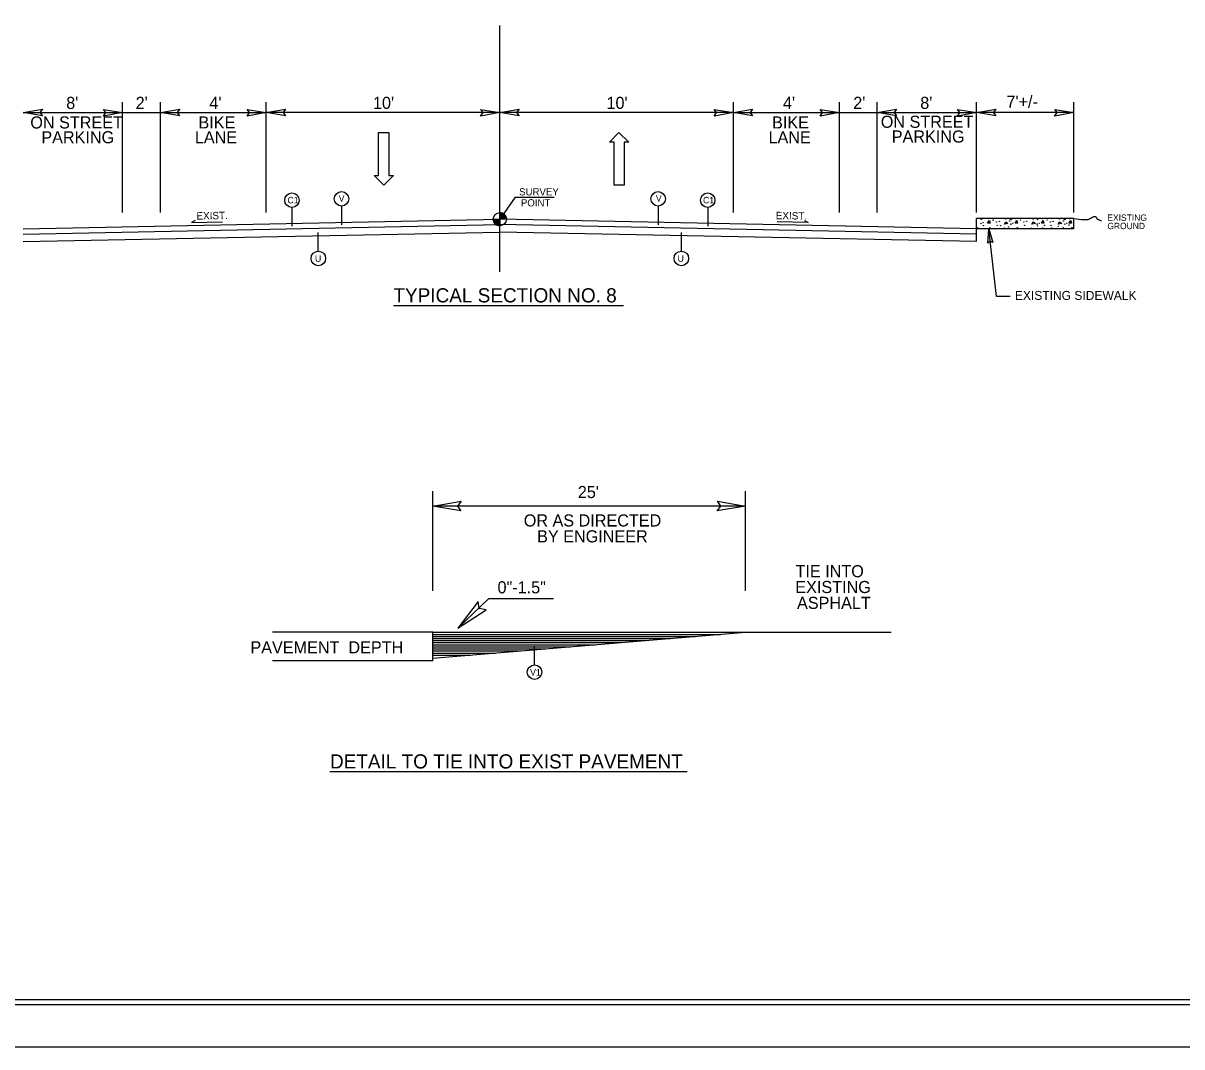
# Model space of a CAD drawing. Extents: x 1022283 to 1026986, y 174822 to 180471.
# Drawn here: x 1023200 to 1024733, y 174822 to 176176 of the extents above; entities that cross this region are included whole.
import ezdxf

# ---------------------------------------------------------------- set-up
doc = ezdxf.new("R2010")
doc.units = 0
for name, color, linetype in [('Default', 7, 'Continuous'), ('Old_Level_3', 7, 'Continuous'), ('Prop Dimension', 7, 'Continuous'), ('Prop Lane Arrow CELL', 7, 'Continuous'), ('Prop Terminator CELL', 7, 'Continuous'), ('Sheet Cutting Line CELL', 7, 'Continuous'), ('Sheet Plot Border Inside CELL', 7, 'Continuous'), ('Sheet Plot Border Outside CELL', 7, 'Continuous'), ('Sheet Typical CELL', 7, 'Continuous'), ('Typical Berm Information CELL', 7, 'Continuous'), ('Typical Curb CELL', 7, 'Continuous'), ('Typical Grade Point Symbol CELL', 7, 'Continuous'), ('Typical ID Circle CELL', 7, 'Continuous'), ('Typical Slope Point Local CELL', 7, 'Continuous'), ('Typical Text General CELL', 7, 'Continuous'), ('Typical Text Grade Point CELL', 7, 'Continuous'), ('Typical Text ID Circle CELL', 7, 'Continuous'), ('Typical Text Label CELL', 7, 'Continuous')]:
    doc.layers.add(name, color=color, linetype=linetype)

# ---------------------------------------------------------------- blocks, each defined once
blk = doc.blocks.new('Lane Arrow Through')
at = {"layer": 'Prop Lane Arrow CELL'}
for p, q in [((-17.15, 1.6), (-3.15, 1.6)), ((-17.15, -1.7), (-17.15, 1.6)), ((-3.15, 1.6), (-3.15, 3.1)), ((-3.15, 3.1), (0, 0)), ((0, 0), (-3.15, -3.2)), ((-3.15, -1.7), (-17.15, -1.7)), ((-3.15, -3.2), (-3.15, -1.7))]:
    blk.add_line(p, q, dxfattribs=at)
blk = doc.blocks.new('Terminator')
at = {"layer": 'Prop Terminator CELL'}
blk.add_lwpolyline([(-9, 1.55), (0, 0), (-9.05, -1.6), (-7.9, 0)], close=True, dxfattribs=at)

msp = doc.modelspace()

# ---------------------------------------------------------------- linework, layer by layer
at = {"layer": 'Default'}
for p, q in [((1023331.7, 175925.5), (1023331.7, 176071.8)), ((1023381.7, 175925.5), (1023381.7, 176071.8)), ((1023521.7, 175925.5), (1023521.7, 176071.8)), ((1023830.5, 175925.5), (1023830.5, 176071.8)), ((1024139.4, 175925.5), (1024139.4, 176071.8)), ((1024279.7, 175925.5), (1024279.7, 176071.8)), ((1024329.7, 175925.5), (1024329.7, 176071.8)), ((1024460.9, 175925.5), (1024460.9, 176071.8)), ((1024589.7, 175925.5), (1024589.7, 176071.8)), ((1024589.7, 175925.5), (1024589.7, 176071.8)), ((1023200.2, 176057.8), (1023331.7, 176057.8)), ((1023331.7, 176057.8), (1023381.7, 176057.8)), ((1023381.7, 176057.8), (1023521.7, 176057.8)), ((1023830.5, 176057.8), (1023521.7, 176057.8)), ((1024139.4, 176057.8), (1023830.5, 176057.8)), ((1024139.4, 176057.8), (1024279.7, 176057.8)), ((1024279.7, 176057.8), (1024329.7, 176057.8)), ((1024329.7, 176057.8), (1024461.3, 176057.8)), ((1024589.7, 176057.8), (1024460.9, 176057.8)), ((1023742, 175425.4), (1023742, 175557.1)), ((1024155.3, 175425.4), (1024155.3, 175557.1)), ((1024155.3, 175537.6), (1023742, 175537.6)), ((1023774.9, 175376.2), (1023816, 175415.5)), ((1023816, 175415.5), (1023901.6, 175415.5))]:
    msp.add_line(p, q, dxfattribs=at)
at = {"layer": 'Old_Level_3'}
for p, q in [((1023742, 175370.7), (1023530, 175370.7)), ((1023742, 175370.7), (1024155.3, 175370.7)), ((1023742, 175370.7), (1024348.1, 175370.7)), ((1023742, 175336.2), (1023742, 175370.7)), ((1023742, 175336.2), (1024155.3, 175370.7)), ((1023742, 175332.9), (1023742, 175370.7)), ((1023742, 175367.9), (1024122.2, 175367.9)), ((1023742, 175365.2), (1024089.1, 175365.2)), ((1023742, 175362.4), (1024056.1, 175362.4)), ((1023742, 175359.7), (1024023, 175359.7)), ((1023742, 175356.9), (1023990, 175356.9)), ((1023742, 175354.1), (1023956.9, 175354.1)), ((1023742, 175351.4), (1023923.8, 175351.4)), ((1023742, 175348.6), (1023890.8, 175348.6)), ((1023742, 175332.9), (1023530, 175332.9)), ((1023742, 175345.9), (1023857.7, 175345.9)), ((1023742, 175343.1), (1023824.7, 175343.1)), ((1023742, 175340.4), (1023791.6, 175340.4))]:
    msp.add_line(p, q, dxfattribs=at)
at = {"layer": 'Prop Dimension'}
for p, q in [((1023830.5, 176082.4), (1023830.5, 176173.1)), ((1023830.5, 176048.4), (1023830.5, 176082.4)), ((1023830.5, 175847.3), (1023830.5, 176048.4)), ((1023850.8, 175946), (1023830.5, 175916.8)), ((1023200.2, 175904.2), (1023830.5, 175916.8)), ((1024460.9, 175904.2), (1023830.5, 175916.8)), ((1023200.2, 175897.2), (1023830.5, 175909.8)), ((1023200.2, 175887.2), (1023830.5, 175899.8)), ((1024460.9, 175897.2), (1023830.5, 175909.8)), ((1024460.9, 175887.2), (1023830.5, 175899.8)), ((1024487.4, 175814.5), (1024477.1, 175904.2)), ((1024505.6, 175814.5), (1024487.4, 175814.5))]:
    msp.add_line(p, q, dxfattribs=at)
at = {"layer": 'Prop Terminator CELL'}
for points in [[(1023225.5, 176053.4), (1023200.2, 176057.8), (1023225.6, 176062.3), (1023222.4, 176057.8)], [(1023306.4, 176062.1), (1023331.7, 176057.8), (1023306.3, 176053.3), (1023309.5, 176057.8)], [(1023407, 176053.4), (1023381.7, 176057.8), (1023407.2, 176062.3), (1023403.9, 176057.8)], [(1023496.4, 176062.1), (1023521.7, 176057.8), (1023496.3, 176053.3), (1023499.5, 176057.8)], [(1023547, 176053.4), (1023521.7, 176057.8), (1023547.2, 176062.3), (1023543.9, 176057.8)], [(1023805.2, 176062.1), (1023830.5, 176057.8), (1023805.1, 176053.3), (1023808.3, 176057.8)], [(1023855.9, 176053.4), (1023830.5, 176057.8), (1023856, 176062.3), (1023852.8, 176057.8)], [(1024114, 176062.1), (1024139.4, 176057.8), (1024113.9, 176053.3), (1024117.1, 176057.8)], [(1024164.7, 176053.4), (1024139.4, 176057.8), (1024164.8, 176062.3), (1024161.6, 176057.8)], [(1024254.4, 176062.1), (1024279.7, 176057.8), (1024254.2, 176053.3), (1024257.5, 176057.8)], [(1024355, 176053.4), (1024329.7, 176057.8), (1024355.1, 176062.3), (1024351.9, 176057.8)], [(1024435.9, 176062.1), (1024461.3, 176057.8), (1024435.8, 176053.3), (1024439, 176057.8)], [(1024486.6, 176053.4), (1024461.3, 176057.8), (1024486.7, 176062.3), (1024483.5, 176057.8)], [(1024564.4, 176062.1), (1024589.7, 176057.8), (1024564.3, 176053.3), (1024567.5, 176057.8)], [(1023779, 175531.2), (1023742, 175537.6), (1023779.2, 175544.2), (1023774.5, 175537.6)], [(1024118.3, 175544), (1024155.3, 175537.6), (1024118, 175531), (1024122.8, 175537.6)], [(1023801.9, 175411.3), (1023774.9, 175376.2), (1023812.4, 175400.2), (1023803.1, 175402.1)]]:
    msp.add_lwpolyline(points, close=True, dxfattribs=at)
at = {"layer": 'Sheet Cutting Line CELL'}
msp.add_line((1022283.2, 174822.5), (1026493.2, 174822.5), dxfattribs=at)
at = {"layer": 'Sheet Plot Border Inside CELL'}
msp.add_lwpolyline([(1026482, 177516.3), (1022315.7, 177516.3), (1022315.7, 174878.6), (1026482, 174878.6)], close=True, dxfattribs=at)
at = {"layer": 'Sheet Plot Border Outside CELL'}
msp.add_lwpolyline([(1026493.2, 177572.5), (1022283.2, 177572.5), (1022283.2, 174822.5), (1026493.2, 174822.5)], close=True, dxfattribs=at)
at = {"layer": 'Sheet Typical CELL'}
msp.add_lwpolyline([(1026450.7, 177510), (1022700.7, 177510), (1022700.7, 174885), (1026450.7, 174885)], close=True, dxfattribs=at)
at = {"layer": 'Typical Berm Information CELL'}
for p, q in [((1023427.7, 175915.1), (1023422.7, 175912.6)), ((1023422.7, 175912.6), (1023463.7, 175913.4)), ((1024238.4, 175912.6), (1024197.4, 175913.4)), ((1024233.4, 175915.1), (1024238.4, 175912.6))]:
    msp.add_line(p, q, dxfattribs=at)
at = {"layer": 'Typical Curb CELL'}
for p, q in [((1024460.9, 175908.1), (1024460.9, 175917.8)), ((1024460.9, 175887.2), (1024460.9, 175917.8)), ((1024460.9, 175908.1), (1024460.9, 175917.8)), ((1024589.7, 175917.8), (1024460.9, 175917.8)), ((1024460.9, 175908.1), (1024460.9, 175917.8)), ((1024460.9, 175887.2), (1024460.9, 175917.8)), ((1024475.5, 175911.6), (1024478, 175915.1)), ((1024478, 175915.1), (1024479, 175911.8)), ((1024497.8, 175910.1), (1024499.6, 175913.4)), ((1024499.6, 175913.4), (1024502.6, 175911.3)), ((1024511.9, 175911.6), (1024514.3, 175915.1)), ((1024514.3, 175915.1), (1024515.3, 175911.8)), ((1024534.1, 175910.1), (1024535.9, 175913.4)), ((1024535.9, 175913.4), (1024538.9, 175911.3)), ((1024546.7, 175911.6), (1024549.2, 175915.1)), ((1024549.2, 175915.1), (1024550.2, 175911.8)), ((1024568.9, 175910.1), (1024570.7, 175913.4)), ((1024570.7, 175913.4), (1024573.7, 175911.3)), ((1024583, 175911.6), (1024585.5, 175915.1)), ((1024585.5, 175915.1), (1024586.5, 175911.8)), ((1024589.7, 175904.2), (1024589.7, 175917.8)), ((1024589.7, 175904.2), (1024460.9, 175904.2)), ((1024479, 175911.8), (1024475.5, 175911.6)), ((1024502.6, 175911.3), (1024497.8, 175910.1)), ((1024515.3, 175911.8), (1024511.9, 175911.6)), ((1024538.9, 175911.3), (1024534.1, 175910.1)), ((1024550.2, 175911.8), (1024546.7, 175911.6)), ((1024573.7, 175911.3), (1024568.9, 175910.1)), ((1024586.5, 175911.8), (1024583, 175911.6))]:
    msp.add_line(p, q, dxfattribs=at)
for centre in [(1024467.3, 175916.8), (1024476.5, 175917.4), (1024483, 175915.6), (1024487.3, 175913.1), (1024491, 175913.9), (1024499.6, 175917.2), (1024504.8, 175914.4), (1024505.2, 175917.2), (1024506.9, 175916.3), (1024512.8, 175917.4), (1024519.3, 175915.6), (1024523.6, 175913.1), (1024527.3, 175913.9), (1024535.9, 175917.2), (1024541.7, 175916.3), (1024547.7, 175917.4), (1024554.2, 175915.6), (1024558.5, 175913.1), (1024562.1, 175913.9), (1024570.8, 175917.2), (1024575.9, 175914.4), (1024576.4, 175917.2), (1024578, 175916.3), (1024584, 175917.4), (1024462.2, 175905.6), (1024466.8, 175910.8), (1024469.6, 175912.1), (1024470, 175908.3), (1024478.6, 175905.5), (1024488.3, 175908.6), (1024492.9, 175908.4), (1024497.5, 175905.3), (1024503.5, 175906.7), (1024506.4, 175910.3), (1024509.2, 175911.6), (1024515, 175905.5), (1024524.6, 175908.6), (1024533.7, 175904.9), (1024541.2, 175910.3), (1024541.6, 175907.8), (1024544, 175911.6), (1024548.6, 175905.3), (1024551.2, 175908.8), (1024559.5, 175908.6), (1024560.4, 175905.3), (1024569, 175907.3), (1024575.6, 175905.6), (1024577.6, 175910.3), (1024580.3, 175911.6), (1024583.3, 175909.3), (1024587.1, 175905.7)]:
    msp.add_circle(centre, 0.233, dxfattribs=at)
at = {"layer": 'Typical Grade Point Symbol CELL'}
for p, q in [((1023821.8, 175916.8), (1023830.5, 175916.8)), ((1023830.5, 175916.8), (1023830.5, 175925.5)), ((1023839.3, 175916.8), (1023830.5, 175916.8)), ((1023830.5, 175908.1), (1023830.5, 175916.8)), ((1023830.5, 175916.8), (1023830.5, 175908.1))]:
    msp.add_line(p, q, dxfattribs=at)
for points in [[(1023821.9, 175916.8), (1023821.9, 175915.8)], [(1023822, 175916.8), (1023822, 175914.8)], [(1023822.2, 175916.8), (1023822.2, 175914.2)], [(1023822.4, 175916.8), (1023822.4, 175913.7)], [(1023822.6, 175916.8), (1023822.6, 175913.3)], [(1023822.7, 175916.8), (1023822.7, 175912.9)], [(1023822.9, 175916.8), (1023822.9, 175912.6)], [(1023823.1, 175916.8), (1023823.1, 175912.3)], [(1023823.3, 175916.8), (1023823.3, 175912)], [(1023823.4, 175916.8), (1023823.4, 175911.7)], [(1023823.6, 175916.8), (1023823.6, 175911.5)], [(1023823.8, 175916.8), (1023823.8, 175911.3)], [(1023824, 175916.8), (1023824, 175911.1)], [(1023824.1, 175916.8), (1023824.1, 175910.9)], [(1023824.3, 175916.8), (1023824.3, 175910.7)], [(1023824.5, 175916.8), (1023824.5, 175910.5)], [(1023824.7, 175916.8), (1023824.7, 175910.4)], [(1023824.8, 175916.8), (1023824.8, 175910.2)], [(1023825, 175916.8), (1023825, 175910.1)], [(1023825.2, 175916.8), (1023825.2, 175909.9)], [(1023825.4, 175916.8), (1023825.4, 175909.8)], [(1023825.5, 175916.8), (1023825.5, 175909.7)], [(1023825.7, 175916.8), (1023825.7, 175909.6)], [(1023825.9, 175916.8), (1023825.9, 175909.4)], [(1023826, 175916.8), (1023826, 175909.3)], [(1023826.2, 175916.8), (1023826.2, 175909.2)], [(1023826.4, 175916.8), (1023826.4, 175909.1)], [(1023826.6, 175916.8), (1023826.6, 175909)], [(1023826.7, 175916.8), (1023826.7, 175909)], [(1023826.9, 175916.8), (1023826.9, 175908.9)], [(1023827.1, 175916.8), (1023827.1, 175908.8)], [(1023827.3, 175916.8), (1023827.3, 175908.7)], [(1023827.4, 175916.8), (1023827.4, 175908.6)], [(1023827.6, 175916.8), (1023827.6, 175908.6)], [(1023827.8, 175916.8), (1023827.8, 175908.5)], [(1023828, 175916.8), (1023828, 175908.5)], [(1023828.1, 175916.8), (1023828.1, 175908.4)], [(1023828.3, 175916.8), (1023828.3, 175908.4)], [(1023828.5, 175916.8), (1023828.5, 175908.3)], [(1023828.7, 175916.8), (1023828.7, 175908.3)], [(1023828.8, 175916.8), (1023828.8, 175908.3)], [(1023829, 175916.8), (1023829, 175908.2)], [(1023829.2, 175916.8), (1023829.2, 175908.2)], [(1023829.4, 175916.8), (1023829.4, 175908.2)], [(1023829.5, 175916.8), (1023829.5, 175908.1)], [(1023829.7, 175916.8), (1023829.7, 175908.1)], [(1023829.9, 175916.8), (1023829.9, 175908.1)], [(1023830.1, 175916.8), (1023830.1, 175908.1)], [(1023830.2, 175916.8), (1023830.2, 175908.1)], [(1023830.4, 175916.8), (1023830.4, 175908.1), (1023830.4, 175908.1)], [(1023830.6, 175925.5), (1023830.6, 175925.5), (1023830.6, 175916.8)], [(1023830.8, 175925.5), (1023830.8, 175916.8)], [(1023831, 175925.5), (1023831, 175916.8)], [(1023831.1, 175925.5), (1023831.1, 175916.8)], [(1023831.3, 175925.5), (1023831.3, 175916.8)], [(1023831.5, 175925.5), (1023831.5, 175916.8)], [(1023831.7, 175925.4), (1023831.7, 175916.8)], [(1023831.8, 175925.4), (1023831.8, 175916.8)], [(1023832, 175925.4), (1023832, 175916.8)], [(1023832.2, 175925.4), (1023832.2, 175916.8)], [(1023832.4, 175925.3), (1023832.4, 175916.8)], [(1023832.5, 175925.3), (1023832.5, 175916.8)], [(1023832.7, 175925.2), (1023832.7, 175916.8)], [(1023832.9, 175925.2), (1023832.9, 175916.8)], [(1023833.1, 175925.1), (1023833.1, 175916.8)], [(1023833.2, 175925.1), (1023833.2, 175916.8)], [(1023833.4, 175925), (1023833.4, 175916.8)], [(1023833.6, 175925), (1023833.6, 175916.8)], [(1023833.8, 175924.9), (1023833.8, 175916.8)], [(1023833.9, 175924.8), (1023833.9, 175916.8)], [(1023834.1, 175924.7), (1023834.1, 175916.8)], [(1023834.3, 175924.7), (1023834.3, 175916.8)], [(1023834.5, 175924.6), (1023834.5, 175916.8)], [(1023834.6, 175924.5), (1023834.6, 175916.8)], [(1023834.8, 175924.4), (1023834.8, 175916.8)], [(1023835, 175924.3), (1023835, 175916.8)], [(1023835.1, 175924.2), (1023835.1, 175916.8)], [(1023835.3, 175924.1), (1023835.3, 175916.8)], [(1023835.5, 175924), (1023835.5, 175916.8)], [(1023835.7, 175923.8), (1023835.7, 175916.8)], [(1023835.8, 175923.7), (1023835.8, 175916.8)], [(1023836, 175923.6), (1023836, 175916.8)], [(1023836.2, 175923.4), (1023836.2, 175916.8)], [(1023836.4, 175923.3), (1023836.4, 175916.8)], [(1023836.5, 175923.1), (1023836.5, 175916.8)], [(1023836.7, 175922.9), (1023836.7, 175916.8)], [(1023836.9, 175922.8), (1023836.9, 175916.8)], [(1023837.1, 175922.6), (1023837.1, 175916.8)], [(1023837.2, 175922.4), (1023837.2, 175916.8)], [(1023837.4, 175922.1), (1023837.4, 175916.8)], [(1023837.6, 175921.9), (1023837.6, 175916.8)], [(1023837.8, 175921.7), (1023837.8, 175916.8)], [(1023837.9, 175921.4), (1023837.9, 175916.8)], [(1023838.1, 175921.1), (1023838.1, 175916.8)], [(1023838.3, 175920.8), (1023838.3, 175916.8)], [(1023838.5, 175920.4), (1023838.5, 175916.8)], [(1023838.6, 175920), (1023838.6, 175916.8)], [(1023838.8, 175919.5), (1023838.8, 175916.8)], [(1023839, 175918.9), (1023839, 175916.8)], [(1023839.2, 175918), (1023839.2, 175916.8)]]:
    msp.add_lwpolyline(points, dxfattribs=at)
msp.add_circle((1023830.5, 175916.8), 8.71, dxfattribs=at)
for start, end in [(179.9905, 269.9905), (359.9905, 89.9905)]:
    msp.add_arc((1023830.5, 175916.8), 8.71, start, end, dxfattribs=at)
at = {"layer": 'Typical ID Circle CELL'}
for p, q in [((1023555.6, 175932.4), (1023555.6, 175907.7)), ((1023621.2, 175934.2), (1023621.2, 175909.5)), ((1024039.9, 175934.2), (1024039.9, 175909.5)), ((1024105.5, 175932.4), (1024105.5, 175907.7)), ((1023590.5, 175874.6), (1023590.5, 175899.3)), ((1024070.6, 175874.6), (1024070.6, 175899.3)), ((1023876.5, 175327.4), (1023876.5, 175352.2))]:
    msp.add_line(p, q, dxfattribs=at)
for centre in [(1023555.6, 175942), (1023621.2, 175943.8), (1024039.9, 175943.8), (1024105.5, 175942), (1023590.5, 175865), (1024070.6, 175865), (1023876.5, 175317.9)]:
    msp.add_circle(centre, 9.59, dxfattribs=at)
at = {"layer": 'Typical Slope Point Local CELL'}
msp.add_lwpolyline([(1024589.7, 175917.8), (1024599.8, 175916.5), (1024602.3, 175916.5), (1024606.1, 175916.5), (1024608.7, 175916.5), (1024611.2, 175917.8), (1024613.7, 175919.1), (1024616.2, 175920.3), (1024618.8, 175920.3), (1024620, 175917.8), (1024622.5, 175916.5), (1024625.1, 175915.3), (1024626.3, 175914.7)], dxfattribs=at)
at = {"layer": 'Typical Text Grade Point CELL'}
msp.add_line((1023850.8, 175946), (1023902.5, 175946), dxfattribs=at)
at = {"layer": 'Typical Text Label CELL'}
for p, q in [((1023689.8, 175802.8), (1023994.2, 175802.8)), ((1023605.9, 175186.5), (1024078.1, 175186.5))]:
    msp.add_line(p, q, dxfattribs=at)

# ---------------------------------------------------------------- block references
at = {"layer": 'Prop Dimension', "xscale": 2.0767499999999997, "yscale": 2.076749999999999, "rotation": 96.5883266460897}
msp.add_blockref('Terminator', (1024477.1, 175904.2), dxfattribs=at)
at = {"layer": 'Prop Lane Arrow CELL', "yscale": 4.059234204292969}
for p, xscale, rotation in [((1023677.2, 175961.7), 4.059234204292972, -89.99999999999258), ((1023988.1, 176031.3), 4.059234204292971, 90.00000000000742)]:
    msp.add_blockref('Lane Arrow Through', p, dxfattribs=dict(at, xscale=xscale, rotation=rotation))

# ---------------------------------------------------------------- texts
at = {"layer": 'Default'}
for s, p in [("25'", (1023933.7, 175548.1)), ('OR AS DIRECTED', (1023862.2, 175510.5)), ('BY ENGINEER', (1023879.9, 175489.5)), ('TIE INTO ', (1024221.6, 175443.4)), ('0"-1.5"', (1023827.5, 175422.1)), ('EXISTING', (1024221.3, 175422.5)), ('ASPHALT', (1024223.6, 175401.5)), ('PAVEMENT  DEPTH', (1023500.7, 175342.7))]:
    msp.add_text(s, height=16, dxfattribs=at).set_placement(p)
at = {"layer": 'Prop Dimension'}
for s, p in [("8'", (1023257.1, 176062.7)), ("2'", (1023348.9, 176062.7)), ("4'", (1023446.4, 176062.7)), ("10'", (1023662.8, 176062.7)), ("10'", (1023971.6, 176062.7)), ("4'", (1024205, 176062.7)), ("2'", (1024298, 176062.7)), ("8'", (1024386.6, 176062.7)), ("7'+/-", (1024500.6, 176064.3)), ('ON STREET', (1023209.6, 176036.8)), ('BIKE', (1023432, 176036.8)), ('BIKE', (1024190.6, 176036.8)), ('ON STREET', (1024334.4, 176037.7)), ('PARKING', (1023224.2, 176017.2)), ('LANE', (1023427.2, 176017.2)), ('LANE', (1024185.9, 176017.2)), ('PARKING', (1024348.9, 176018.2))]:
    msp.add_text(s, height=16, dxfattribs=at).set_placement(p)
at = {"layer": 'Typical Berm Information CELL'}
for rotation, p in [(0.9927, (1023429.4, 175916.3)), (359.0073, (1024195.4, 175916.9))]:
    msp.add_text('EXIST.', height=9.79, rotation=rotation, dxfattribs=at).set_placement(p)
at = {"layer": 'Typical Slope Point Local CELL'}
for s, p in [('EXISTING ', (1024634, 175914.7)), ('GROUND', (1024634, 175903.7))]:
    msp.add_text(s, height=8.38, dxfattribs=at).set_placement(p)
at = {"layer": 'Typical Text General CELL'}
msp.add_text('EXISTING SIDEWALK', height=11.898, dxfattribs=at).set_placement((1024511.7, 175810.1))
at = {"layer": 'Typical Text Grade Point CELL'}
for s, p in [('SURVEY', (1023856.1, 175948.3)), ('POINT', (1023858.4, 175933.8))]:
    msp.add_text(s, height=9.53, dxfattribs=at).set_placement(p)
at = {"layer": 'Typical Text ID Circle CELL'}
for s, p in [('C1', (1023549.7, 175937.8)), ('V', (1023617.4, 175940)), ('V', (1024036.9, 175940)), ('C1', (1024099.3, 175937.8)), ('U', (1023586.1, 175860.4)), ('U', (1024065.7, 175860.4)), ('V1', (1023870.6, 175313.3))]:
    msp.add_text(s, height=8.58, dxfattribs=at).set_placement(p)
at = {"layer": 'Typical Text Label CELL'}
for s, p in [('TYPICAL SECTION NO. 8', (1023689.8, 175806.8)), ('DETAIL TO TIE INTO EXIST PAVEMENT', (1023605.9, 175190.5))]:
    msp.add_text(s, height=18.75, dxfattribs=at).set_placement(p)

doc.saveas('drawing.dxf')
